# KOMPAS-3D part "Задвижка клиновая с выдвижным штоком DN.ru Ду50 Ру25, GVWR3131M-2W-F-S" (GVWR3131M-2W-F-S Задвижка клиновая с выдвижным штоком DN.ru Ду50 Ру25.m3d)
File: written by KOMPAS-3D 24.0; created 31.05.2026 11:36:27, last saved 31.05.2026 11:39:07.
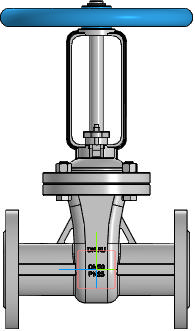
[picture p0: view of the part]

Document properties: Автор: R2D2; Полное имя файла: E:\Работа\Зайцев\GVWR3131M-2W-F-S Задвижка клиновая 30нж64нж DN.ru  Ду50-150 Ру25\исходные данные\DN50\dn50\GVWR3131M-2W-F-S Задвижка клиновая с выдвижным штоком DN.ru Ду50 Ру25.m3d

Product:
- Part/product: Задвижка клиновая с выдвижным штоком DN.ru Ду50 Ру25  | designation GVWR3131M-2W-F-S
    Масса: 14
    Раздел спецификации: Прочие изделия
    Примечание: D040-08600

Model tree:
1. Операция без истории:1

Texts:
  GVWR3131M-2W-F-S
